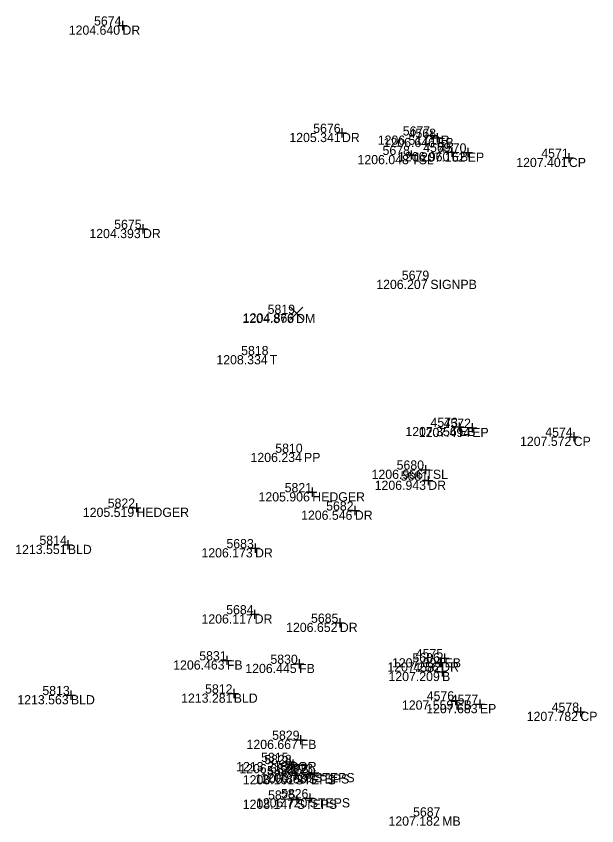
# Model space of a CAD drawing. Extents: x 2044997 to 2050342, y 455233 to 458054.
# Drawn here: x 2047574.7 to 2047637.8, y 456833.6 to 456921.6 of the extents above; entities that cross this region are included whole.
import ezdxf

# ---------------------------------------------------------------- set-up
doc = ezdxf.new("R2010")
doc.units = 0
for name, color, linetype in [('SV_X_Random_Point', 7, 'Continuous'), ('SV_X_Shot_Marker', 7, 'Continuous'), ('SV_X_Text_Comment', 7, 'Continuous'), ('SV_X_Text_Elevation', 7, 'Continuous'), ('SV_X_Text_Name', 7, 'Continuous')]:
    doc.layers.add(name, color=color, linetype=linetype)

msp = doc.modelspace()

# ---------------------------------------------------------------- linework, layer by layer
at = {"layer": 'SV_X_Random_Point'}
for p, q in [((2047604.482, 456888.61), (2047605.815, 456889.945)), ((2047604.482, 456889.945), (2047605.815, 456888.61))]:
    msp.add_line(p, q, dxfattribs=at)
at = {"layer": 'SV_X_Shot_Marker'}
for p, q in [((2047586.222, 456921.04), (2047586.222, 456920.04)), ((2047585.722, 456920.54), (2047586.722, 456920.54)), ((2047586.222, 456920.54), (2047586.222, 456920.54)), ((2047609.579, 456908.878), (2047610.579, 456908.878)), ((2047610.079, 456909.378), (2047610.079, 456908.378)), ((2047610.079, 456908.878), (2047610.079, 456908.878)), ((2047619.349, 456908.587), (2047620.349, 456908.587)), ((2047619.849, 456909.087), (2047619.849, 456908.087)), ((2047619.849, 456908.587), (2047619.849, 456908.587)), ((2047620.445, 456908.833), (2047620.445, 456907.833)), ((2047619.945, 456908.333), (2047620.945, 456908.333)), ((2047620.445, 456908.333), (2047620.445, 456908.333)), ((2047617.609, 456906.975), (2047617.609, 456905.975)), ((2047622.011, 456907.293), (2047622.011, 456906.293)), ((2047623.753, 456907.242), (2047623.753, 456906.242)), ((2047617.109, 456906.475), (2047618.109, 456906.475)), ((2047617.609, 456906.475), (2047617.609, 456906.475)), ((2047621.511, 456906.793), (2047622.511, 456906.793)), ((2047622.011, 456906.793), (2047622.011, 456906.793)), ((2047623.253, 456906.742), (2047624.253, 456906.742)), ((2047623.753, 456906.742), (2047623.753, 456906.742)), ((2047634.243, 456906.164), (2047635.243, 456906.164)), ((2047634.743, 456906.664), (2047634.743, 456905.664)), ((2047634.743, 456906.164), (2047634.743, 456906.164)), ((2047588.453, 456898.942), (2047588.453, 456897.942)), ((2047587.953, 456898.442), (2047588.953, 456898.442)), ((2047588.453, 456898.442), (2047588.453, 456898.442)), ((2047622.313, 456876.928), (2047623.313, 456876.928)), ((2047622.813, 456877.428), (2047622.813, 456876.428)), ((2047622.813, 456876.928), (2047622.813, 456876.928)), ((2047624.241, 456877.333), (2047624.241, 456876.333)), ((2047623.741, 456876.833), (2047624.741, 456876.833)), ((2047624.241, 456876.833), (2047624.241, 456876.833)), ((2047635.268, 456876.364), (2047635.268, 456875.364)), ((2047634.768, 456875.864), (2047635.768, 456875.864)), ((2047635.268, 456875.864), (2047635.268, 456875.864)), ((2047619.145, 456872.788), (2047619.145, 456871.788)), ((2047618.645, 456872.288), (2047619.645, 456872.288)), ((2047619.145, 456872.288), (2047619.145, 456872.288)), ((2047618.964, 456871.095), (2047619.964, 456871.095)), ((2047619.464, 456871.595), (2047619.464, 456870.595)), ((2047619.464, 456871.095), (2047619.464, 456871.095)), ((2047606.854, 456870.336), (2047606.854, 456869.336)), ((2047606.354, 456869.836), (2047607.354, 456869.836)), ((2047606.854, 456869.836), (2047606.854, 456869.836)), ((2047587.236, 456868.154), (2047588.236, 456868.154)), ((2047587.736, 456868.654), (2047587.736, 456867.654)), ((2047587.736, 456868.154), (2047587.736, 456868.154)), ((2047611.48, 456868.341), (2047611.48, 456867.341)), ((2047610.98, 456867.841), (2047611.98, 456867.841)), ((2047611.48, 456867.841), (2047611.48, 456867.841)), ((2047580.286, 456864.622), (2047580.286, 456863.622)), ((2047579.786, 456864.122), (2047580.786, 456864.122)), ((2047580.286, 456864.122), (2047580.286, 456864.122)), ((2047600.132, 456863.754), (2047601.132, 456863.754)), ((2047600.632, 456864.254), (2047600.632, 456863.254)), ((2047600.632, 456863.754), (2047600.632, 456863.754)), ((2047600.588, 456857.075), (2047600.588, 456856.075)), ((2047600.088, 456856.575), (2047601.088, 456856.575)), ((2047600.588, 456856.575), (2047600.588, 456856.575)), ((2047609.846, 456856.153), (2047609.846, 456855.153)), ((2047609.346, 456855.653), (2047610.346, 456855.653)), ((2047609.846, 456855.653), (2047609.846, 456855.653)), ((2047621.235, 456852.302), (2047621.235, 456851.302)), ((2047597.068, 456851.569), (2047598.068, 456851.569)), ((2047597.568, 456852.069), (2047597.568, 456851.069)), ((2047597.568, 456851.569), (2047597.568, 456851.569)), ((2047605.421, 456851.693), (2047605.421, 456850.693)), ((2047620.735, 456851.802), (2047621.735, 456851.802)), ((2047620.86, 456851.852), (2047620.86, 456850.852)), ((2047621.235, 456851.802), (2047621.235, 456851.802)), ((2047604.921, 456851.193), (2047605.921, 456851.193)), ((2047605.421, 456851.193), (2047605.421, 456851.193)), ((2047620.36, 456851.352), (2047621.36, 456851.352)), ((2047620.86, 456851.352), (2047620.86, 456851.352)), ((2047620.955, 456850.82), (2047620.955, 456849.82)), ((2047620.455, 456850.32), (2047621.455, 456850.32)), ((2047620.955, 456850.32), (2047620.955, 456850.32)), ((2047580.623, 456848.292), (2047580.623, 456847.292)), ((2047597.818, 456847.965), (2047598.818, 456847.965)), ((2047598.318, 456848.465), (2047598.318, 456847.465)), ((2047598.318, 456847.965), (2047598.318, 456847.965)), ((2047580.123, 456847.792), (2047581.123, 456847.792)), ((2047580.623, 456847.792), (2047580.623, 456847.792)), ((2047621.919, 456847.216), (2047622.919, 456847.216)), ((2047622.419, 456847.716), (2047622.419, 456846.716)), ((2047622.419, 456847.216), (2047622.419, 456847.216)), ((2047625.069, 456847.326), (2047625.069, 456846.326)), ((2047624.569, 456846.826), (2047625.569, 456846.826)), ((2047625.069, 456846.826), (2047625.069, 456846.826)), ((2047635.994, 456846.485), (2047635.994, 456845.485)), ((2047635.494, 456845.985), (2047636.494, 456845.985)), ((2047635.994, 456845.985), (2047635.994, 456845.985)), ((2047605.089, 456842.938), (2047606.089, 456842.938)), ((2047605.589, 456843.438), (2047605.589, 456842.438)), ((2047605.589, 456842.938), (2047605.589, 456842.938)), ((2047604.42, 456841.032), (2047604.42, 456840.032)), ((2047603.92, 456840.532), (2047604.92, 456840.532)), ((2047604.256, 456840.302), (2047605.256, 456840.302)), ((2047604.42, 456840.532), (2047604.42, 456840.532)), ((2047604.756, 456840.802), (2047604.756, 456839.802)), ((2047604.756, 456840.302), (2047604.756, 456840.302)), ((2047604.518, 456839.095), (2047605.518, 456839.095)), ((2047605.018, 456839.595), (2047605.018, 456838.595)), ((2047605.018, 456839.095), (2047605.018, 456839.095)), ((2047605.987, 456839.192), (2047606.987, 456839.192)), ((2047606.487, 456839.692), (2047606.487, 456838.692)), ((2047606.487, 456839.192), (2047606.487, 456839.192)), ((2047606.573, 456839.335), (2047607.573, 456839.335)), ((2047607.073, 456839.835), (2047607.073, 456838.835)), ((2047607.073, 456839.335), (2047607.073, 456839.335)), ((2047605.174, 456836.937), (2047605.174, 456835.937)), ((2047606.076, 456836.596), (2047607.076, 456836.596)), ((2047606.576, 456837.096), (2047606.576, 456836.096)), ((2047606.576, 456836.596), (2047606.576, 456836.596)), ((2047604.674, 456836.437), (2047605.674, 456836.437)), ((2047605.174, 456836.437), (2047605.174, 456836.437))]:
    msp.add_line(p, q, dxfattribs=at)

# ---------------------------------------------------------------- texts
at = {"layer": 'SV_X_Text_Comment'}
for s, p in [('DR', (2047586.222, 456919.54)), ('DR', (2047610.079, 456907.878)), ('DR', (2047619.849, 456907.587)), ('EB', (2047620.445, 456907.333)), ('TSL', (2047617.609, 456905.475)), ('EB', (2047622.011, 456905.793)), ('EP', (2047623.753, 456905.742)), ('CP', (2047634.743, 456905.164)), ('DR', (2047588.453, 456897.442)), ('SIGNPB', (2047619.688, 456891.915)), ('DM', (2047605.1, 456888.215)), ('T', (2047602.24, 456883.73)), ('EB', (2047622.813, 456875.928)), ('EP', (2047624.241, 456875.833)), ('CP', (2047635.268, 456874.864)), ('PP', (2047605.953, 456873.117)), ('TSL', (2047619.145, 456871.288)), ('DR', (2047619.464, 456870.095)), ('HEDGER', (2047606.854, 456868.836)), ('HEDGER', (2047587.736, 456867.154)), ('DR', (2047611.48, 456866.841)), ('BLD', (2047580.286, 456863.122)), ('DR', (2047600.632, 456862.754)), ('DR', (2047600.588, 456855.575)), ('DR', (2047609.846, 456854.653)), ('FB', (2047597.568, 456850.569)), ('EB', (2047621.235, 456850.802)), ('FB', (2047605.421, 456850.193)), ('DR', (2047620.86, 456850.352)), ('B', (2047620.955, 456849.32)), ('BLD', (2047598.318, 456846.965)), ('BLD', (2047580.623, 456846.792)), ('EB', (2047622.419, 456846.216)), ('EP', (2047625.069, 456845.826)), ('CP', (2047635.994, 456844.985)), ('FB', (2047605.589, 456841.938)), ('POR', (2047604.42, 456839.532)), ('FB', (2047604.756, 456839.302)), ('STEPS', (2047605.018, 456838.095)), ('STEPS', (2047606.487, 456838.192)), ('STEPS', (2047607.073, 456838.335)), ('STEPS', (2047606.576, 456835.596)), ('STEPS', (2047605.174, 456835.437)), ('MB', (2047620.971, 456833.61))]:
    msp.add_text(s, height=1, dxfattribs=at).set_placement(p)
at = {"layer": 'SV_X_Text_Elevation'}
for s, p in [('1204.640', (2047580.385, 456919.54)), ('1205.341', (2047604.362, 456907.878)), ('1206.517', (2047613.969, 456907.587)), ('1206.646', (2047614.604, 456907.333)), ('1206.048', (2047611.773, 456905.475)), ('1206.960', (2047616.174, 456905.793)), ('1207.162', (2047617.92, 456905.742)), ('1207.401', (2047629.025, 456905.164)), ('1204.393', (2047582.626, 456897.442)), ('1206.207', (2047613.808, 456891.915)), ('1204.876', (2047599.26, 456888.215)), ('1204.866', (2047599.308, 456888.277)), ('1208.334', (2047596.432, 456883.73)), ('1207.356', (2047616.973, 456875.928)), ('1207.494', (2047618.433, 456875.833)), ('1207.572', (2047629.435, 456874.864)), ('1206.234', (2047600.145, 456873.117)), ('1206.956', (2047613.304, 456871.288)), ('1206.943', (2047613.638, 456870.095)), ('1205.906', (2047601.013, 456868.836)), ('1205.519', (2047581.918, 456867.154)), ('1206.546', (2047605.639, 456866.841)), ('1213.551', (2047574.568, 456863.122)), ('1206.173', (2047594.806, 456862.754)), ('1206.117', (2047594.812, 456855.575)), ('1206.652', (2047604.013, 456854.653)), ('1206.463', (2047591.741, 456850.569)), ('1207.391', (2047615.518, 456850.802)), ('1206.445', (2047599.574, 456850.193)), ('1207.256', (2047615.019, 456850.352)), ('1207.209', (2047615.137, 456849.32)), ('1213.281', (2047592.6, 456846.965)), ('1213.563', (2047574.797, 456846.792)), ('1207.559', (2047616.601, 456846.216)), ('1207.683', (2047619.242, 456845.826)), ('1207.782', (2047630.161, 456844.985)), ('1206.667', (2047599.71, 456841.938)), ('1213.218', (2047598.584, 456839.532)), ('1206.682', (2047598.923, 456839.302)), ('1208.161', (2047599.301, 456838.095)), ('1206.808', (2047600.65, 456838.192)), ('1206.720', (2047601.235, 456838.335)), ('1206.720', (2047600.738, 456835.596)), ('1208.147', (2047599.295, 456835.437)), ('1207.182', (2047615.138, 456833.61))]:
    msp.add_text(s, height=1, dxfattribs=at).set_placement(p)
at = {"layer": 'SV_X_Text_Name'}
for s, p in [('5674', (2047583.132, 456920.54)), ('5676', (2047606.956, 456908.878)), ('5677', (2047616.687, 456908.587)), ('4568', (2047617.327, 456908.333)), ('4569', (2047618.911, 456906.793)), ('4570', (2047620.634, 456906.742)), ('5678', (2047614.491, 456906.475)), ('4571', (2047631.743, 456906.164)), ('5675', (2047585.323, 456898.442)), ('5679', (2047616.588, 456892.915)), ('5819', (2047602.001, 456889.215)), ('5818', (2047599.122, 456884.73)), ('4573', (2047619.705, 456876.928)), ('4572', (2047621.125, 456876.833)), ('4574', (2047632.178, 456875.864)), ('5810', (2047602.833, 456874.117)), ('5680', (2047616.025, 456872.288)), ('5681', (2047616.465, 456871.095)), ('5821', (2047603.854, 456869.836)), ('5822', (2047584.62, 456868.154)), ('5682', (2047608.365, 456867.841)), ('5814', (2047577.196, 456864.122)), ('5683', (2047597.524, 456863.754)), ('5684', (2047597.498, 456856.575)), ('5685', (2047606.716, 456855.653)), ('5831', (2047594.568, 456851.569)), ('5686', (2047617.737, 456851.352)), ('4575', (2047618.106, 456851.802)), ('5830', (2047602.302, 456851.193)), ('4582', (2047617.84, 456850.32)), ('5813', (2047577.515, 456847.792)), ('5812', (2047595.203, 456847.965)), ('4576', (2047619.297, 456847.216)), ('4577', (2047621.907, 456846.826)), ('4578', (2047632.876, 456845.985)), ('5829', (2047602.49, 456842.938)), ('5815', (2047601.291, 456840.532)), ('5828', (2047601.638, 456840.302)), ('5824', (2047601.928, 456839.095)), ('5827', (2047603.325, 456839.192)), ('5823', (2047603.964, 456839.335)), ('5825', (2047602.045, 456836.437)), ('5826', (2047603.453, 456836.596)), ('5687', (2047617.81, 456834.61))]:
    msp.add_text(s, height=1, dxfattribs=at).set_placement(p)

doc.saveas('drawing.dxf')
